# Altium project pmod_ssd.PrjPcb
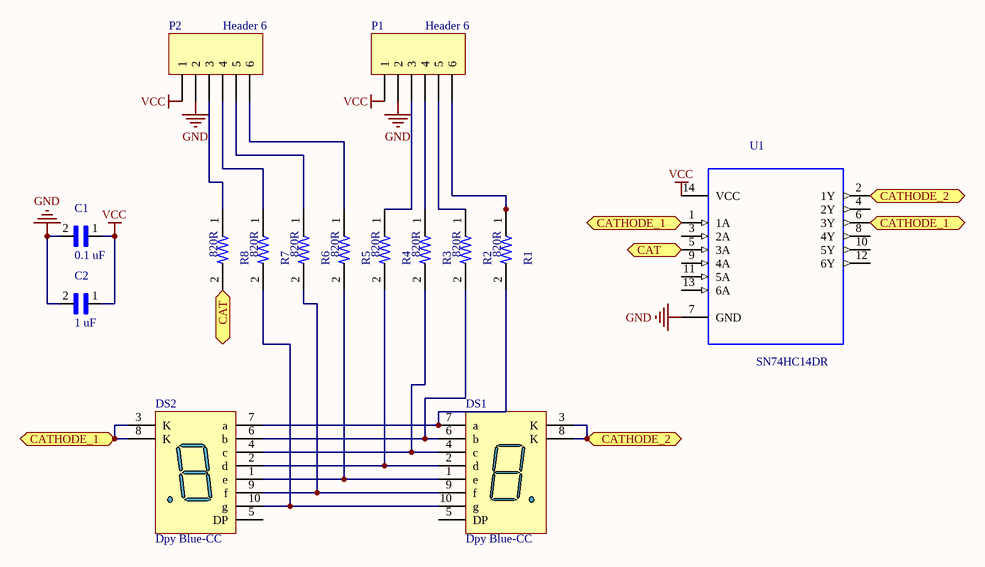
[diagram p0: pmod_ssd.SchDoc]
1 sheet, 15 parts. Net scope: flat (ports and power ports of the same name join across sheets).
Board file: pmod_ssd.PcbDoc

## Sheet pmod_ssd.SchDoc
size A4

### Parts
C1  0.1 uF  [CAPC320160X94]
C2  1 uF  [CAPC320160X94]
DS1  Dpy Blue-CC  [H]
DS2  Dpy Blue-CC  [H]
P1  Header 6  [HDR1X6]
P2  Header 6  [HDR1X6]
R1  820R  [RESC3216X70]
R2  820R  [RESC3216X70]
R3  820R  [RESC3216X70]
R4  820R  [RESC3216X70]
R5  820R  [RESC3216X70]
R6  820R  [RESC3216X70]
R7  820R  [RESC3216X70]
R8  820R  [RESC3216X70]
U1  SN74HC14DR  [SOIC127P600X175-14N]

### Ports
CAT (bidir), CATHODE_1 (in), CATHODE_1 (out), CATHODE_2 (in), CATHODE_2 (out)

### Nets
GND: C1.2 C2.2 P1.2 P2.2 U1.7(GND)
VCC: C1.1 C2.1 P1.1 P2.1 U1.14(VCC)
NetDS1_1: DS1.1(e) DS2.1(e) R5.2
NetDS1_2: DS1.2(d) DS2.2(d) R4.2
NetDS1_3: DS1.3(K) DS1.8(K) U1.2(1Y) ; port CATHODE_2
NetDS1_4: DS1.4(c) DS2.4(c) R3.2
NetDS1_6: DS1.6(b) DS2.6(b) R2.2
NetDS1_7: DS1.7(a) DS2.7(a) R1.2
NetDS1_9: DS1.9(f) DS2.9(f) R6.2
NetDS1_10: DS1.10(g) DS2.10(g) R7.2
NetDS2_3: DS2.3(K) DS2.8(K) U1.1(1A) U1.6(3Y) ; port CATHODE_1
NetP1_3: P1.3 R4.1
NetP1_4: P1.4 R3.1
NetP1_5: P1.5 R2.1
NetP1_6: P1.6 R1.1
NetP2_3: P2.3 R8.1
NetP2_4: P2.4 R7.1
NetP2_5: P2.5 R6.1
NetP2_6: P2.6 R5.1
NetR8_2: R8.2 U1.5(3A) ; port CAT

Not connected (* = marked no-connect by the designer): DS1 5(DP); DS2 5(DP); U1 3(2A) 4(2Y) 8(4Y) 9(4A) 10(5Y) 11(5A) 12(6Y) 13(6A)

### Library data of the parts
C1 C2 = 12061C683KAT2A: 1206 68 nF 100 V Â±10 % Tolerance X7R Surface Mount Multilayer Ceramic Capacitor; MF: AVX
DS1 DS2 = Dpy Blue-CC: 14.2 mm General Purpose Blue 7-Segment Display: CC, RH DP, Gray Surface; MinimumIntensity: 2020 ucd; Note: IF = 10 mA
P1 P2 = Header 6: Header, 6-Pin
R1-R8 = ERA-8AED3011V: Res Thin Film 1206 3.01K Ohm 0.5% 1/4W Â±25ppm/Â°C Molded SMD SMD Punched Carrier T/R; MF: Panasonic
U1 = SN74HC14DR: Inverter Schmitt Trigger 6-Element CMOS 14-Pin SOIC T/R; MF: Texas Instruments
